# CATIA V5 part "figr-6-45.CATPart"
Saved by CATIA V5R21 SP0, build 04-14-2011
Part number: Part1
Bounding box of the stored display mesh (mm): x -26.811 to 26.811, y -47.298 to 47.298, z 0 to 31.431
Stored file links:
  D:\CATIA V5R21 E-RESOURCES\CATIA-V5R21\catia-v5r21-prt\c06-catia-v5r21-prt\c06-catia-v5r21-figr-6-45.CATPart
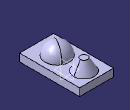
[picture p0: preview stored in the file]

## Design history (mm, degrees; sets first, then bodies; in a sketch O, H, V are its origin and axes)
Body1 (main body)
  Sketch1 on xy-plane, origin (0, 0, 0), H (1, 0, 0), V (0, 1, 0)
    line L1 (-26.8114, 47.2981) -> (26.8114, 47.2981)
    line L2 (26.8114, 47.2981) -> (26.8114, -47.2981)
    line L3 (26.8114, -47.2981) -> (-26.8114, -47.2981)
    line L4 (-26.8114, -47.2981) -> (-26.8114, 47.2981)
    axis line L5 (26.8114, -47.2981) -> (-26.8114, 47.2981)
    horizontal: L1 H, L3 H
    vertical: L2 V, L4 V
    coincidence: L5 O
    midpoint: L5 O
  Pad1: profile Sketch1, direction (0, 0, 1), length 12
  Sketch2 on yz-plane, origin (0, 0, 0), H (0, 1, 0), V (0, 0, 1)
    axis line L1 (-14.846, 35.4307) -> (-14.846, -5.9324)
    arc A1 centre (-14.846, 12.2093) radius 19.2216 from (-14.846, 31.431) to (-33.1926, 6.476) ccw
    point P3 (-14.846, 12.2093)
    point P4 (-14.846, 31.431)
    line L2 (-14.846, 31.431) -> (-14.846, 8.3996)
    line L3 (-14.846, 8.3996) -> (-33.1926, 6.476)
    vertical: L1 V, L2 V
    coincidence: P3 L1, P4 L1, A1 O
  Shaft1: profile Sketch2, axis Sketch2.L1, angle 360
  Sketch3 on face of Pad1, origin (0, 0, 12), H (1, 0, 0), V (0, 1, 0)
    circle A1 centre (0, 27.4246) radius 16.1543
    point P1 (0, 27.4246)
    coincidence: P1 V
  Pad2: profile Sketch3, direction (0, 0, 1), length 18
  Draft1: Angle 30, Neutral face of Pad1, PullDir face of Pad1, SupportToDraft face of Pad2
